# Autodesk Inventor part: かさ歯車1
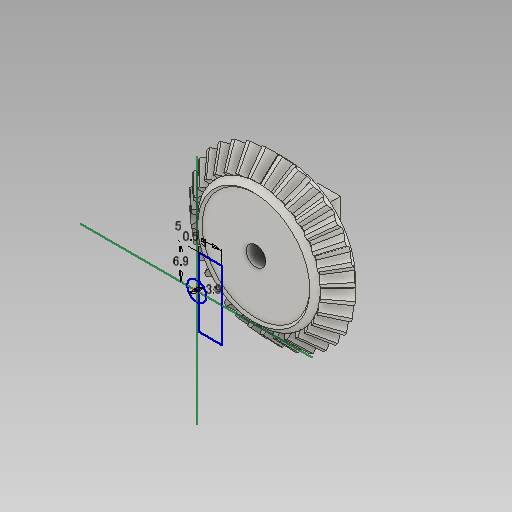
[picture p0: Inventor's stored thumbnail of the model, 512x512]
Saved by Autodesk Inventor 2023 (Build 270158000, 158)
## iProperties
CustomPartVersion: 1
Created: 2024-05
Part Number: かさ歯車1
Material: Steel, Mild
Document SubType Name: Modeling
Designer: kumagai
Categories: <?xml version="1.0" encoding="UTF-16"?> <MemberInstance><Categories><FamilyTemplate><FamilyTemplateParameter ValueType="xs:double" Id="1" ObjectReferenceKey="da
Mass: 60.9118 g
Surface Area: 34.3074 cm^2
Volume: 7.7496 cm^3
Density: 7.86 g/cm^3
Appearance: Steel
Author: kumagai
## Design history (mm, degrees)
node "上側の点"
node "メッシュ平面2"
sketch "歯のボディ スケッチ"
  geometry: L1 (0, 0)-(15.151, -16.849); L2 (15.151, -16.849)-(16.707, -15.293); L3 (16.707, -15.293)-(0, 0); L4 (16, -16)-(0, 0); L5 (11.803, -13.125)-(13.015, -11.914); L6 (15.151, -16.849)-(11.803, -13.125); L7 (16.707, -15.293)-(13.015, -11.914); L8 (0, -39.387)-(0, 6.564) reference; L9 (0, -16)-(16.707, -16)
  constraints: 16 end point, 4 point on line, 3 perpendicular, 2 collinear, 1 horizontal alignment, 1 vertical alignment
  dimensions: "d0" = 32 diameter of L4.start L8 (= da_de); "d1" = 30.30294 diameter of L1.end L8 (= da_dfe); "d2" = 33.41421 diameter of L2.end L8 (= da_dae); "d3" = 5 distance between parallel lines of L2 L5 (= da_b); "d4" = 15.29289 vertical distance of L2.end L1.start (= da_ve)
revolve "歯のボディ" sketch "歯のボディ スケッチ" stored, may be unused: angle "d5" = 90 deg
node "始点"
node "歯の平面"
sketch "開始スケッチ"
  geometry: L1 (0, -23.505)-(0, 10.645) reference; L2 (-0.366, -1.464)-(0.366, -1.464); A1 r 8.083 centre (-8.298, -3.019) between (-0.366, -1.464) and (-1.666, 1.603); A2 r 8.083 centre (8.298, -3.019) between (1.666, 1.603) and (0.366, -1.464); A3 r 24.287 centre (0, -22.627) between (1.666, 1.603) and (-1.666, 1.603); 1 further point
  constraints: 6 point on circle, 3 centre point, 3 symmetric about line, 2 end point, 1 coincident, 1 perpendicular, 1 other
  dimensions: "d7" = 8.08317 radius of A1 (= fd_rr); "d8" = 8.29774 horizontal distance of point (0, -22.627) A1.centre (= fd_x); "d9" = 19.60833 vertical distance of point (0, -22.627) A1.centre (= fd_y); "d57" = 24.28742 radius of A3 (= 0.5 x fd_dva + 0.3 x da_he); "d58" = 21.16342 distance from line of A3.centre L2 (= 0.5 x fd_dva - 1.12 x da_he)
node "終了側の点"
  node "終了平面"
sketch "終了側スケッチ"
  geometry: L1 (0, -15.354)-(0, 6.953) reference; L2 (-0.283, -1.133)-(0.283, -1.133); A1 r 6.258 centre (-6.424, -2.337) between (-0.283, -1.133) and (-1.29, 1.241); A2 r 6.258 centre (6.424, -2.337) between (1.29, 1.241) and (0.283, -1.133); A3 r 18.803 centre (0, -17.517) between (1.29, 1.241) and (-1.29, 1.241); 1 further point
  constraints: 6 point on circle, 3 centre point, 3 symmetric about line, 2 end point, 1 coincident, 1 other
  dimensions: "d12" = 6.25773 radius of A1 (computed from fd_rr, fd_ratio); "d15" = 6.42384 horizontal distance of A1.centre point (0, -17.517) (computed from fd_x, fd_ratio); "d16" = 15.18014 vertical distance of A1.centre point (0, -17.517) (computed from fd_y, fd_ratio); "d59" = 18.80254 radius of A3 (computed from d57, fd_ratio); "d60" = 16.38404 distance from line of A3.centre L2 (computed from d58, fd_ratio)
feature "Loft" sketch "終了側スケッチ" dims "d17" = 0, "d18" = 90 deg, "d19" = 0, "d20" = 90 deg, "d89" = 0, "da_teethtype" = 0 [user parameter]
sketch "3D スケッチ(右)"
  node "Helical Curve Right" dims "d65" = 173.72889 (computed from da_dm, da_delta, da_beta), "d66" = 31.5, "d67" = 32 (= da_de), "d68" = -45 deg (= -da_delta), "d69" = 3.61332 (computed from fd_loft, da_delta)
node "終了平面(右)"
sketch "終了側スケッチ(右)"
  geometry: L1 (0, -23.46)-(0, 9.709) reference; L2 (-0.283, -1.133)-(0.283, -1.133); A1 r 6.258 centre (-6.424, -2.337) between (-0.283, -1.133) and (-1.29, 1.241); A2 r 6.258 centre (6.424, -2.337) between (1.29, 1.241) and (0.283, -1.133); A3 r 18.803 centre (0, -17.517) between (1.29, 1.241) and (-1.29, 1.241); 1 further point
  constraints: 6 point on circle, 3 centre point, 3 symmetric about line, 2 end point, 1 coincident, 1 perpendicular, 1 other
  dimensions: "d70" = 6.42384 horizontal distance of A3.centre A1.centre (computed from fd_x, fd_ratio); "d71" = 15.18014 vertical distance of point (0, -17.517) A1.centre (computed from fd_y, fd_ratio); "d72" = 6.25773 radius of A1 (computed from fd_rr, fd_ratio); "d73" = 16.38404 distance from line of point (0, -17.517) L2 (computed from d58, fd_ratio); "d74" = 18.80254 radius of A3 (computed from d57, fd_ratio)
feature "ロフト(右)" sketch "終了側スケッチ(右)" dims "d75" = 0, "d77" = 0, "d79" = 0, "d80" = 90 deg, "d85" = 20, "d92" = 90 deg, "d93" = 90 deg, "da_teethtype" = 0 [user parameter]
sketch "3D スケッチ(左)"
  node "Helical Curve Left" dims "d26" = 173.72889 (computed from da_dm, da_delta, da_beta), "d27" = 3.61332 (computed from fd_loft, da_delta), "d28" = 32 (= da_de), "d29" = -45 deg (= -da_delta)
node "終了平面(左)"
sketch "終了側スケッチ(左)" dims "d56" = 9.20604 (derived)
  geometry: L1 (0, -29.116)-(0, 12.094) reference; L2 (-0.283, -1.128)-(0.283, -1.128); A1 r 6.258 centre (-6.424, -2.332) between (-0.283, -1.128) and (-1.29, 1.246); A2 r 6.258 centre (6.424, -2.332) between (1.29, 1.246) and (0.283, -1.128); A3 r 18.803 centre (0, -17.512) between (1.29, 1.246) and (-1.29, 1.246); 2 further points; 1 other entity
  constraints: 6 point on circle, 3 centre point, 3 symmetric about line, 2 end point, 1 coincident, 2 other
  dimensions: "d30" = 6.25773 radius of A1 (computed from fd_rr, fd_ratio); "d31" = 6.42384 horizontal distance of point (0, -17.512) A1.centre (computed from fd_x, fd_ratio); "d32" = 15.18014 vertical distance of A1.centre point (0, -17.512) (computed from fd_y, fd_ratio); "d61" = 18.80254 radius of A3 (computed from d57, fd_ratio); "d62" = 16.38404 distance from line of point (0, -17.512) L2 (computed from d58, fd_ratio)
feature "ロフト(左)" sketch "終了側スケッチ(左)" dims "d35" = 0, "d37" = 0, "d39" = 0, "d40" = 90 deg, "d84" = 10, "d90" = 90 deg, "d91" = 90 deg, "da_teethtype" = 0 [user parameter]
sketch "ボディ スケッチ"
  geometry: L1 (0, -35.038)-(0, -19.531) reference; L2 (15.151, -16.849)-(11.803, -13.125) reference; L3 (11.803, -13.125)-(0, -13.125); L4 (15.151, -16.849)-(0, -16.849); L5 (16, -16)-(0, 0) reference; L6 (11.803, -13.125)-(13.015, -11.914) reference; L7 (0, 0)-(15.151, -16.849) reference; L8 (12.323, -12.606)-(10.909, -14.02); L9 (10.909, -14.02)-(9.848, -12.959); L10 (9.848, -12.959)-(11.262, -11.545); L11 (11.262, -11.545)-(12.323, -12.606); L12 (15.151, -16.849)-(14, -18); L13 (14, -18)-(0, -18); L14 (0, -18)-(0, -16.849); L15 (0, -12)-(0, -13.125); L16 (10.808, -12)-(0, -12); 2 further points
  constraints: 22 end point, 6 point on line, 3 parallel, 2 horizontal, 2 perpendicular, 1 collinear
  dimensions: "d94" = 0.2 distance between parallel lines of L11 L5; "d95" = 1.5 distance between parallel lines of L6 L10; "d96" = 2 distance between parallel lines of L9 L11; "d97" = 18 distance from line of L5.end L13; "d98" = 14 distance from line of L1 L12.end; "d102" = 12 distance from line of L5.end L16
revolve "固定ボディ" sketch "ボディ スケッチ" stored, may be unused: angle "d46" = 360 deg
sketch "Sketch6"
  geometry: L1 (16, -16)-(0, 0) reference; L2 (0, -37.8)-(0, 6.3) reference
feature "ピッチ円直径" sketch "Sketch6" dims angle "d47" = 90 deg
sketch "スケッチ8"
  geometry: L1 (0.5, 6.9)-(5, 6.9); L2 (5, 6.9)-(5, -6.9); L3 (5, -6.9)-(0.5, -6.9); L4 (0.5, -6.9)-(0.5, 6.9); L5 (-23.373, 0)-(23.373, 0) reference; L6 (0, 23.371)-(0, -23.372) reference; C1 r 1.95 at (0, 0); 3 further points
  constraints: 8 end point, 1 centre point, 1 coincident, 1 other
  dimensions: "d99" = 3.9 diameter of C1; "d104" = 6.9 distance between parallel lines of L5 L1; "d105" = 0.5 distance between parallel lines of L6 L4; "d106" = 5 distance between parallel lines of L6 L2
extrude "押し出し1" cut sketch "スケッチ8" extent not by distance; stored distance "d100" = 0; taper "d101" = 0 deg
extrude "押し出し2" join sketch "スケッチ8" stored distance "d107" = 6; taper "d108" = 0 deg
sketch "スケッチ10"
  geometry: L1 (-14, -18)-(14, -18) reference; L2 (-1.885, -18)-(-6.9, -18) reference; L3 (-6.9, -18)-(6.9, -18) reference; L4 (6.9, -18)-(1.885, -18) reference; L5 (1.885, -18)-(-1.885, -18) reference; L6 (0, 4.8)-(0, -28.8) reference; L7 (0, -28.8)-(0, 4.8) reference; C1 r 1.6 at (-3.7, -21); C2 r 1.6 at (3.7, -21); 1 further point
  constraints: 2 centre point, 1 other
  dimensions: "d109" = 3 distance from line of L1 C1.centre; "d110" = 3.2 diameter of C1; "d111" = 3.7 distance from line of L6 C1.centre
extrude "押し出し3" cut sketch "スケッチ10" extent not by distance; stored distance "d112" = 0; taper "d113" = 0 deg
pattern_circular "円形状パターン4" dims angle "d115" = 360 deg
body "Solid1"
pattern_circular "Circular Pattern" dims angle "d22" = 360 deg, "d88" = 0, "da_teethtype" = 0 [user parameter]
pattern_circular "放射状パターン(右)" dims angle "d82" = 360 deg, "da_teethtype" = 0 [user parameter]
pattern_circular "放射状パターン(左)" dims angle "d42" = 360 deg, "da_teethtype" = 0 [user parameter]
body "Srf1"
node "投影ループ1"
other parameters: "da_b" = 5 [user parameter; used in 2 equation terms], "da_de" = 32 [user parameter; used in 4 equation terms], "da_dae" = 33.41421 [user parameter; used in 2 equation terms], "da_dfe" = 30.30294 [user parameter; used in 1 equation term], "da_le" = 22.62742 [user parameter; used in 1 equation term], "da_omega" = 90 deg [user parameter; used in 1 equation term], "da_beta" = 0 [user parameter; used in 2 equation terms], "da_delta" = 45 deg [user parameter; used in 8 equation terms], "da_alpha" = 20 deg [user parameter; used in 2 equation terms], "da_he" = 2.2 [user parameter; used in 4 equation terms], "da_ve" = 15.29289 [user parameter; used in 1 equation term], "fd_dv" = 45.25483 (computed from da_de, da_delta) [user parameter; used in 1 equation term], "fd_dva" = 47.25483 (computed from da_dae, da_delta) [user parameter; used in 3 equation terms], "fd_dvb" = 42.52563 (computed from fd_dv, da_alpha) [user parameter; used in 2 equation terms], "da_zv" = 452.54834 [user parameter; used in 1 equation term], "fd_loft" = 5.11 (= da_b + 0.05 x da_he) [user parameter; used in 4 equation terms], "fd_ratio" = 7.74168 (computed from da_le, fd_loft) [user parameter; used in 15 equation terms], "fd_rr" = 8.08317 (computed from fd_dd, fd_dvb) [user parameter; used in 6 equation terms], "fd_angle" = 0.35096 (computed from da_zv) [user parameter; used in 4 equation terms], "fd_x1" = 0.79396 (computed from da_dvw, fd_angle) [user parameter; used in 1 equation term], "fd_y1" = 22.61348 (computed from da_dvw, fd_angle) [user parameter; used in 1 equation term], "fd_x2" = 7.50378 (computed from fd_rr, fd_angle2, fd_angle) [user parameter; used in 1 equation term], "fd_y2" = 3.00515 (computed from fd_rr, fd_angle2, fd_angle) [user parameter; used in 1 equation term], "fd_x" = 8.29774 (= fd_x1 + fd_x2) [user parameter; used in 4 equation terms], "fd_y" = 19.60833 (= fd_y1 - fd_y2) [user parameter; used in 4 equation terms], "fd_angle2" = 3.45829 (computed from fd_dvb, fd_dd, da_alpha) [user parameter; used in 2 equation terms], "fd_dd" = 45.49483 (= fd_dva - 0.8 x da_he) [user parameter; used in 2 equation terms], "da_dvw" = 45.25483 [user parameter; used in 2 equation terms], "d11" = 5.11 (= fd_loft), "da_dm" = 28.46447 [user parameter; used in 2 equation terms], "da_x" = 0 [user parameter], "da_m" = 1 [user parameter], "d48" = 0, "d49" = 0, "d50" = 90 deg (= da_omega), "d51" = 0.98175 (computed from da_z), "d52" = 0, "d53" = 0, "d54" = 0
